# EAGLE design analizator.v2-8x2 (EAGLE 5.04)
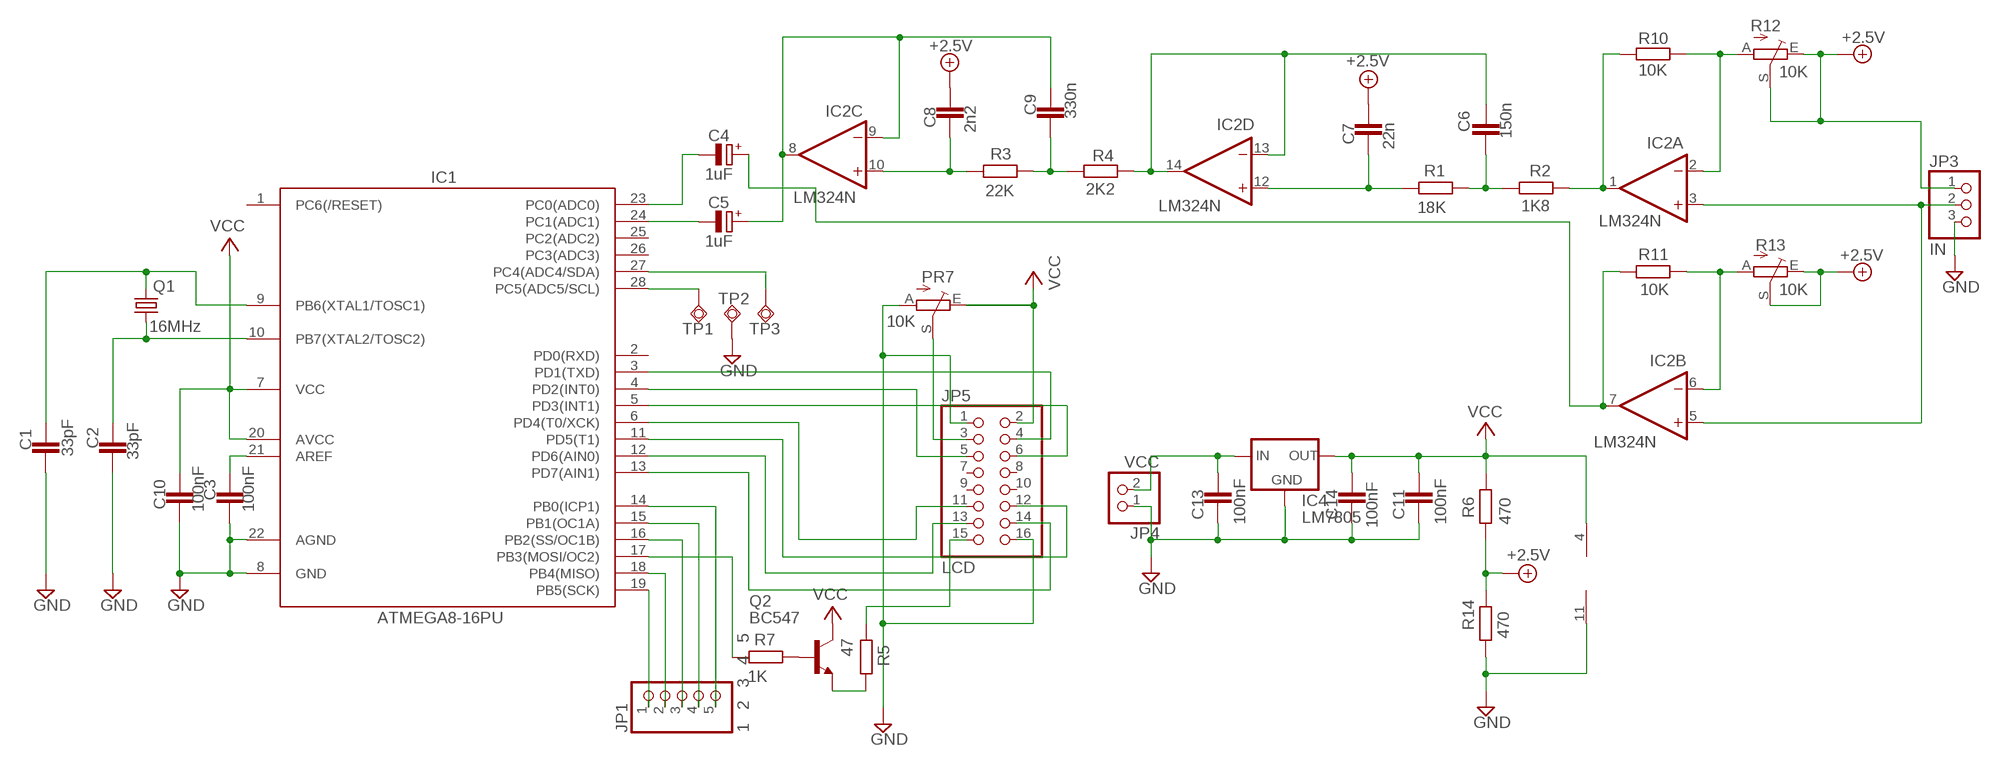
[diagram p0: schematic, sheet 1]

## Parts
C1  33pF  C-EU025-024X044  [C025-024X044]
C2  33pF  C-EU025-024X044  [C025-024X044]
C3  100nF  C-EU050-025X075  [C050-025X075]
C4  1uF  CPOL-EUE5-4  [E5-4]
C5  1uF  CPOL-EUE5-4  [E5-4]
C6  150n  C-EU050-025X075  [C050-025X075]
C7  22n  C-EU050-025X075  [C050-025X075]
C8  2n2  C-EU050-025X075  [C050-025X075]
C9  330n  C-EU050-025X075  [C050-025X075]
C10  100nF  C-EU050-025X075  [C050-025X075]
C11  100nF  C-EU050-025X075  [C050-025X075]
C13  100nF  C-EU050-025X075  [C050-025X075]
C14  100nF  C-EU050-025X075  [C050-025X075]
IC1  ATMEGA8-16PU  ATMEGA8-PU  [DIL28-3]
IC2  LM324N  [DIL14]
IC4  LM7805  78XXL  [78XXL]
JP1  1 2 3 4 5  PINHD-1X5  [1X05]
JP3  IN  PINHD-1X3  [1X03]
JP4  VCC  PINHD-1X2  [1X02]
JP5  LCD  PINHD-2X8  [2X08]
PR7  10K  TRIM_EU-CA6V  [CA6V]
Q1  16MHz  CRYTALHC49S  [HC49/S]
Q2  BC547  [TO92]
R1  18K  R-EU_0204/7  [0204/7]
R2  1K8  R-EU_0204/7  [0204/7]
R3  22K  R-EU_0204/7  [0204/7]
R4  2K2  R-EU_0204/7  [0204/7]
R5  47  R-EU_0204/7  [0204/7]
R6  470  R-EU_0204/7  [0204/7]
R7  1K  R-EU_0204/7  [0204/7]
R10  10K  R-EU_0204/7  [0204/7]
R11  10K  R-EU_0204/7  [0204/7]
R12  10K  TRIM_EU-CA6V  [CA6V]
R13  10K  TRIM_EU-CA6V  [CA6V]
R14  470  R-EU_0204/7  [0204/7]
TP1  TPSQTP11SQ  [TP11SQ]
TP2  TPSQTP11SQ  [TP11SQ]
TP3  TPSQTP11SQ  [TP11SQ]

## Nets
+5V: C7.1 C8.1 JP3.1 R6.1 R12.E R12.S R13.E R13.S R14.2 ; supply symbol labelled +2.5V
GND: C1.1 C2.1 C3.1 C10.1 C11.2 C13.2 C14.2 IC1.8(GND) IC1.22(AGND) IC2.11(P:V-) IC4.GND JP3.3 JP4.1 JP5.1 JP5.16 PR7.A R14.1 TP2.TP
N$1: C1.2 IC1.9(PB6(XTAL1/TOSC1)) Q1.2
N$2: C2.2 IC1.10(PB7(XTAL2/TOSC2)) Q1.1
N$3: C4.- IC1.23(PC0(ADC0))
N$4: C3.2 IC1.21(AREF)
N$5: C5.- IC1.24(PC1(ADC1))
N$6: C6.2 IC2.13(D:-IN) IC2.14(D:OUT) R4.2
N$7: C5.+ C9.2 IC2.8(C:OUT) IC2.9(C:-IN)
N$8: JP5.3 PR7.S
N$9: C7.2 IC2.12(D:+IN) R1.1
N$10: C6.1 R1.2 R2.1
N$11: IC1.3(PD1(TXD)) JP5.4
N$12: C8.2 IC2.10(C:+IN) R3.1
N$13: C9.1 R3.2 R4.1
N$14: IC1.4(PD2(INT0)) JP5.5
N$15: IC2.2(A:-IN) R10.2 R12.A
N$16: IC2.6(B:-IN) R11.2 R13.A
N$17: IC1.5(PD3(INT1)) JP5.6
N$18: IC1.6(PD4(T0/XCK)) JP5.11
N$19: IC1.11(PD5(T1)) JP5.12
N$20: IC1.12(PD6(AIN0)) JP5.13
N$21: IC1.13(PD7(AIN1)) JP5.14
N$22: IC1.17(PB3(MOSI/OC2)) R7.1
N$23: Q2.1(E) R5.2
N$24: IC2.3(A:+IN) IC2.5(B:+IN) JP3.2
N$25: Q2.2(B) R7.2
N$26: IC2.1(A:OUT) R2.2 R10.1
N$27: C4.+ IC2.7(B:OUT) R11.1
N$28: IC1.19(PB5(SCK)) JP1.1
N$29: JP5.15 R5.1
N$30: IC1.18(PB4(MISO)) JP1.2
N$31: IC1.16(PB2(SS/OC1B)) JP1.3
N$32: IC1.15(PB1(OC1A)) JP1.4
N$33: IC1.28(PC5(ADC5/SCL)) TP1.TP
N$38: IC1.14(PB0(ICP1)) JP1.5
N$39: IC1.27(PC4(ADC4/SDA)) TP3.TP
NS$28: C13.1 IC4.IN JP4.2
VCC: C10.2 C11.1 C14.1 IC1.7(VCC) IC1.20(AVCC) IC2.4(P:V+) IC4.OUT JP5.2 PR7.E Q2.3(C) R6.2
Unconnected: IC1.1(PC6(/RESET)) IC1.2(PD0(RXD)) IC1.25(PC2(ADC2)) IC1.26(PC3(ADC3)) JP5.7 JP5.8 JP5.9 JP5.10

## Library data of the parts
C1-C3 C6-C11 C13 C14 = rcl:C-EU: CAPACITOR, European symbol
C4 C5 = rcl:CPOL-EU: POLARIZED CAPACITOR, European symbol
IC1 = atmega8:ATMEGA8-PU
IC2 = linear:LM324: OP AMP
IC4 = v-reg:78XXL: VOLTAGE REGULATOR
JP1 = pinhead:PINHD-1X5: PIN HEADER
JP3 = pinhead:PINHD-1X3: PIN HEADER
JP4 = pinhead:PINHD-1X2: PIN HEADER
JP5 = pinhead:PINHD-2X8: PIN HEADER
PR7 R12 R13 = pot:TRIM_EU-: POTENTIOMETER
Q1 = crystal:CRYTAL: CRYSTAL
Q2 = transistor-npn:BC547*: NPN Transistor
R1-R7 R10 R11 R14 = rcl:R-EU_: RESISTOR, European symbol
TP1-TP3 = testpad:TPSQ

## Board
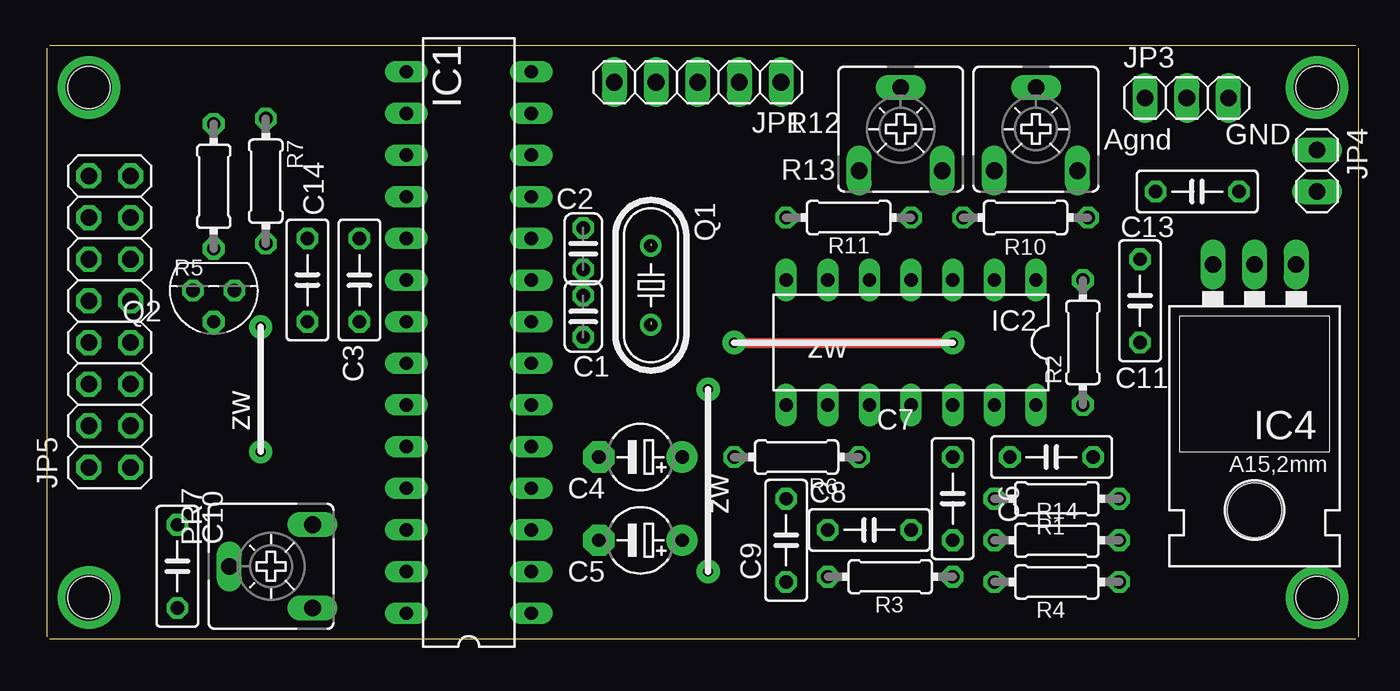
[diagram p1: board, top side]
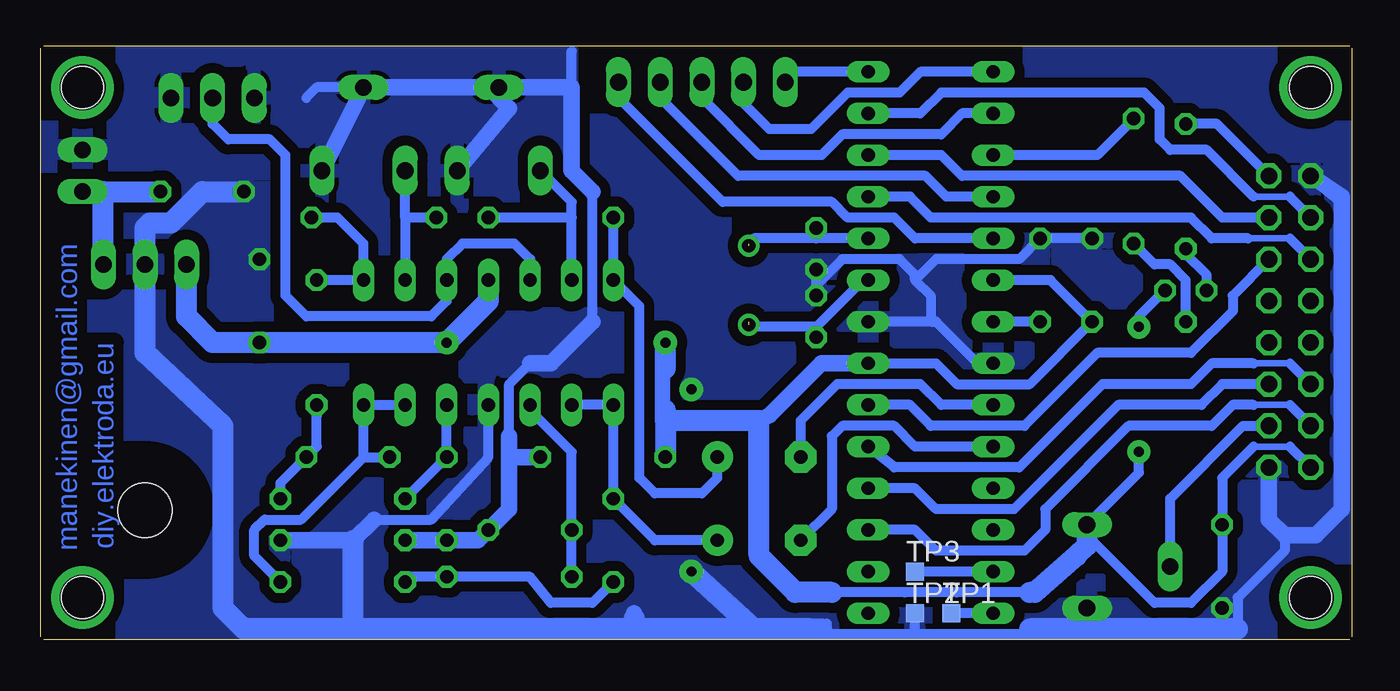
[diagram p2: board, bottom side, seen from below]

Size 80.01 x 36.2 mm. Coordinates in mm from the lower left corner, seen from the top.
Outline: 0,0.17 0,36.04
Outline: 79.85,36.2 0.17,36.2
Outline: 79.85,0 0.17,0
Outline: 80.01,0.17 80.01,36.04
Copper layers (1*16): Top 0.035mm / dielectric 1.5mm / Bottom 0.035mm
Design rules "default *": minimum track width 10mil, minimum drill 24mil, track to track 24mil, track to pad 24mil, pad to pad 24mil, via to via 24mil, smd to smd 24mil, copper to edge 1mil, drill to drill 8mil, minimum pad ring 10mil, minimum via ring 8mil, stop-mask expansion 4mil, vias tented up to drill 0mil, thermal gap 10mil
Holes 2.54 mm at 2.54,33.66 2.54,2.55 77.47,2.55 77.47,33.66

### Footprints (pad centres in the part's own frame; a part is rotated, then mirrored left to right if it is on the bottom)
C025-024X044 = drill 0.813 octagon: 1 -1.27,0; 2 1.27,0
C050-025X075 = drill 0.813 octagon: 1 -2.54,0; 2 2.54,0
E5-4 = drill 0.813 pad 1.905 round: + -2.54,0 | drill 0.813 pad 1.905 octagon: - 2.54,0
DIL28-3 = drill 0.813 long: 1 -16.51,-3.81; 2 -13.97,-3.81; 3 -11.43,-3.81; 4 -8.89,-3.81; 5 -6.35,-3.81; 6 -3.81,-3.81; 7 -1.27,-3.81; 8 1.27,-3.81; 9 3.81,-3.81; 10 6.35,-3.81; 11 8.89,-3.81; 12 11.43,-3.81; 13 13.97,-3.81; 14 16.51,-3.81; 15 16.51,3.81; 16 13.97,3.81; 17 11.43,3.81; 18 8.89,3.81; 19 6.35,3.81; 20 3.81,3.81; 21 1.27,3.81; 22 -1.27,3.81; 23 -3.81,3.81; 24 -6.35,3.81; 25 -8.89,3.81; 26 -11.43,3.81; 27 -13.97,3.81; 28 -16.51,3.81
DIL14 = drill 0.813 long: 1 -7.62,-3.81; 2 -5.08,-3.81; 3 -2.54,-3.81; 4 0,-3.81; 5 2.54,-3.81; 6 5.08,-3.81; 7 7.62,-3.81; 8 7.62,3.81; 9 5.08,3.81; 10 2.54,3.81; 11 0,3.81; 12 -2.54,3.81; 13 -5.08,3.81; 14 -7.62,3.81
78XXL = drill 1.016 long: GND 0,-3.81; IN -2.54,-3.81; OUT 2.54,-3.81 | hole 3.302: 0,11.176
1X05 = drill 1.016 long: 1 -5.08,0; 2 -2.54,0; 3 0,0; 4 2.54,0; 5 5.08,0
1X03 = drill 1.016 long: 1 -2.54,0; 2 0,0; 3 2.54,0
1X02 = drill 1.016 long: 1 -1.27,0; 2 1.27,0
2X08 = drill 1.016 octagon: 1 -8.89,-1.27; 2 -8.89,1.27; 3 -6.35,-1.27; 4 -6.35,1.27; 5 -3.81,-1.27; 6 -3.81,1.27; 7 -1.27,-1.27; 8 -1.27,1.27; 9 1.27,-1.27; 10 1.27,1.27; 11 3.81,-1.27; 12 3.81,1.27; 13 6.35,-1.27; 14 6.35,1.27; 15 8.89,-1.27; 16 8.89,1.27
CA6V = drill 1.016 long: A -2.54,-2.54; E 2.54,-2.54; S 0,2.54
HC49/S = drill 0.813 round: 1 -2.413,0; 2 2.413,0
TO92 = drill 0.813 octagon: 1 1.27,0; 2 0,1.905; 3 -1.27,0
0204/7 = drill 0.813 octagon: 1 -3.81,0; 2 3.81,0
TP11SQ = smd 1.1 x 1.1: TP 0,0

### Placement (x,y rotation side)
C1  32.71,19.69 270 top
C2  32.71,23.82 90 top
C3  19.05,21.91 270 top
C4  36.2,11.12 180 top
C5  36.2,6.04 180 top
C6  61.28,11.12 180 top
C7  55.25,8.58 90 top
C8  50.17,6.67 180 top
C9  45.09,6.04 90 top
C10  7.94,4.45 90 top
C11  66.68,20.64 90 top
C13  70.17,27.31 180 top
C14  15.88,21.91 90 top
IC1  25.72,18.1 90 top
IC2  52.71,18.1 180 top
IC4  73.67,19.05 180 top
JP1  39.69,33.98 180 top
JP3  69.54,33.02 0 top
JP4  77.47,28.58 270 top
JP5  3.82,19.37 90 top
PR7  13.66,4.45 90 top
Q1  36.84,21.6 270 top
Q2  10.16,21.28 180 top
R1  61.6,8.58 0 top
R2  63.19,18.1 90 top
R3  51.44,3.81 0 top
R4  61.6,3.5 0 top
R5  10.16,27.63 270 top
R6  45.73,11.12 180 top
R7  13.34,27.95 270 top
R10  59.7,25.72 180 top
R11  48.9,25.72 0 top
R12  60.33,31.12 0 top
R13  52.08,31.12 0 top
R14  61.6,6.04 180 top
TP1  24.45,1.59 0 bottom
TP2  26.68,1.59 0 bottom
TP3  26.68,4.13 0 bottom

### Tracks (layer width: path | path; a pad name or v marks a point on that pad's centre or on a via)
+5V
  Bottom 0.61: 46.36,19.37 46.36,27.31 | 50.17,16.83 51.44,15.56 51.44,12.39 | R12.S 63.19,33.66 63.82,33.02 | 47.63,33.66 47.63,35.88
  Bottom 1.016: 52.71,33.66 R13.S 47.63,33.66 47.63,28.58 46.36,27.31 | 52.71,33.66 R12.S R12.E | R13.E 51.44,32.39 52.71,33.66 | 46.36,19.37 48.9,16.83 50.17,16.83 | 51.44,11.12 51.44,7.94 C8.1 53.34,6.04 C7.1 R14.2 | 51.44,11.12 51.44,12.39 | 51.44,11.12 R6.1
  pour Bottom: 44.45,20.64 53.98,20.64 53.98,15.56 44.45,15.56
  pour Bottom: 67.31,36.2 64.78,20.64 47.63,20.64 47.63,35.88
GND  (via drill 0.6 pad 1.42)
  Top 0.406: v40.33,4.13 v40.33,15.24
  Bottom 0.61: IC1.22 22.86,16.83 25.41,19.37 25.72,19.37 | 25.72,19.37 IC1.8 | IC2.11 52.71,11.12 56.2,7.31 59.7,7.31 | 26.68,21.91 25.41,23.18 20.32,23.18 C3.1 C14.2 | 32.71,21.6 31.12,23.18 27.63,23.18 26.68,22.23 26.68,21.91 | 32.71,21.6 C2.1 | 32.71,21.6 C1.1 | 32.07,0.96 33.02,0.64 32.07,0.32 26.68,0.32 | 26.68,0.32 20.01,0.32 19.69,0.64 6.99,0.64 6.99,1.91 | 26.68,21.91 25.72,20.96 25.72,19.37 | 6.99,1.91 C10.1 | 6.99,1.91 6.99,2.55 4.13,5.4 4.13,6.36 | 16.2,0.64 PR7.A | 26.68,0.32 TP2.TP
  Bottom 0.813: JP5.16 0.96,26.99
  Bottom 1.016: 59.7,7.31 60.96,6.04 R14.1 | 43.82,1.27 43.82,1.59 | JP5.16 0.64,26.99 0.64,7.94 2.23,6.36 4.13,6.36 5.08,7.31 JP5.1
  Bottom 1.27: 32.39,0.64 33.02,0.64 36.52,0.64 | 36.52,0.64 43.82,0.64 | 43.82,0.64 43.82,1.27 | 43.82,0.64 60.96,0.64 | 60.96,0.64 67.63,0.64 68.9,1.91 68.9,13.02 73.67,17.47 73.67,25.09 73.35,25.41 72.08,25.41 70.17,27.31 C13.2 | 60.96,0.64 60.96,6.04 | 6.99,0.64 16.2,0.64 19.69,0.64 | 36.52,0.64 v40.33,4.13
  pour Bottom: -0.63,35.88 -0.63,0.32 80.02,0.32 80.02,35.88
N$1  (1 unrouted)
  Bottom 0.61: IC1.9 29.85,21.91 32.71,19.05 | C1.2 32.71,19.05 | 32.71,19.05 36.52,19.05 36.84,19.37
N$2  (1 unrouted)
  Bottom 0.61: IC1.10 32.71,24.45 | 32.71,24.45 C2.2 | 32.71,24.45 36.52,24.45 36.84,24.14
N$3
  Bottom 0.61: IC1.23 25.09,14.29 26.36,15.56 31.44,15.56 33.66,13.34 C4.-
N$4
  Bottom 0.61: C3.2 IC1.21
N$5
  Bottom 0.61: IC1.24 26.68,11.75 27.95,13.02 31.12,13.02 31.76,12.39 31.76,7.94 C5.-
N$6
  Bottom 0.61: R4.2 67,5.09 67,6.67 66.36,7.31 64.14,7.31 60.33,11.12 | IC2.13 IC2.14 60.33,11.12 | 60.33,11.12 C6.2
N$7
  Bottom 0.61: C5.+ 42.55,6.04 C9.2 IC2.8 IC2.9
N$8
  Bottom 0.61: PR7.S 11.12,8.58 6.67,13.02 JP5.3
N$9
  Bottom 0.61: IC2.12 C7.2 R1.1
N$10
  Bottom 0.61: 63.19,13.66 R2.1 63.19,11.75 C6.1 65.41,9.53 R1.2
N$11
  Bottom 0.406: 3.82,14.29 6.04,14.29
  Bottom 0.61: IC1.3 26.68,6.67 25.41,5.4 20.01,5.4 18.74,6.67 18.74,7.94 13.66,13.02 8.58,13.02 7.31,14.29 6.04,14.29 | JP5.4 3.82,14.29
N$12
  Bottom 0.61: IC2.10 50.17,13.97 47.63,11.44 C8.2 R3.1
N$13
  Bottom 0.61: C9.1 46.36,2.23 48.9,2.23 50.17,3.81 R3.2 57.16,3.81 57.47,3.81 R4.1
N$14
  Bottom 0.61: IC1.4 26.68,9.21 25.41,7.94 20.64,7.94 14.29,14.29 9.21,14.29 7.94,15.56 JP5.5
N$15
  Bottom 0.61: 57.79,25.72 IC2.2 | 57.79,25.72 R12.A | R10.2 57.79,25.72
N$16
  Bottom 0.61: IC2.6 47.63,25.72 | 47.63,25.72 47.63,26.68 R13.A | 47.63,25.72 R11.2
N$17
  Bottom 0.406: 3.82,16.83 6.04,16.83
  Bottom 0.61: IC1.5 27.95,10.48 20.32,10.48 15.25,15.56 9.85,15.56 8.58,16.83 6.04,16.83 | JP5.6 3.82,16.83
N$18
  Bottom 0.61: IC1.6 26.99,14.29 25.72,13.02 20.01,13.02 15.56,17.47 9.85,17.47 7.31,20.01 7.31,20.96 JP5.11
N$19
  Bottom 0.406: 3.82,24.45 6.36,24.45
  Bottom 0.61: IC1.11 26.99,26.99 25.72,25.72 9.85,25.72 8.58,24.45 6.36,24.45 | JP5.12 3.82,24.45
N$20
  Bottom 0.61: IC1.12 25.09,29.53 23.82,28.26 10.48,28.26 7.94,25.72 JP5.13
N$21
  Bottom 0.406: 3.82,26.99 6.04,26.99
  Bottom 0.61: IC1.13 26.36,32.07 25.09,33.34 12.71,33.34 11.75,32.39 11.75,30.48 11.12,29.85 8.89,29.85 6.04,26.99 | JP5.14 3.82,26.99
N$22
  Bottom 0.61: R7.1 15.56,29.53 IC1.17
N$23
  Bottom 0.61: Q2.1 8.89,22.23 10.16,23.5 R5.2
N$24
  Bottom 0.61: IC2.5 50.17,23.18 51.12,24.14 54.3,24.14 55.25,23.18 IC2.3 55.25,20.64 56.2,19.69 63.82,19.69 65.09,20.96 65.09,29.53 66.05,30.48 68.58,30.48 69.54,31.44 JP3.2
N$25
  Bottom 0.61: R7.2 12.71,23.5 12.07,22.87 11.12,22.87 10.16,21.91 Q2.2
N$26
  Bottom 0.61: R2.2 IC2.1 60.33,24.14 61.92,25.72 R10.1
N$27
  Bottom 0.61: C4.+ 38.74,9.85 39.69,8.89 42.55,8.89 43.5,9.85 43.5,20.33 IC2.7 R11.1
N$28
  Bottom 0.61: IC1.19 26.68,24.45 27.95,25.72 30.8,25.72 31.76,26.68 38.42,26.68 44.77,33.02 JP1.1
N$29
  Bottom 0.61: JP5.15 8.26,31.44 R5.1
N$30
  Bottom 0.61: IC1.18 24.77,26.99 26.04,28.26 37.47,28.26 42.23,33.02 JP1.2
N$31
  Bottom 0.61: IC1.16 23.82,32.07 25.09,30.8 31.12,30.8 32.39,29.53 36.2,29.53 39.69,33.02 JP1.3
N$32
  Bottom 0.61: IC1.15 26.36,34.61 27.63,33.34 30.8,33.34 33.02,31.12 35.56,31.12 37.15,32.71 JP1.4
N$33
  Bottom 0.61: IC1.28 TP1.TP
N$34  (via drill 2.8 pad 2.54)
  other vias: 2.54,33.66
N$35  (via drill 2.8 pad 2.54)
  other vias: 77.47,33.66
N$36  (via drill 2.8 pad 2.54)
  other vias: 2.54,2.55
N$37  (via drill 2.8 pad 2.54)
  other vias: 77.47,2.55
N$38
  Bottom 0.61: IC1.14 33.98,34.61 JP1.5
N$39
  Bottom 0.61: IC1.27 TP3.TP
NS$28
  Bottom 1.27: 76.2,27.31 C13.1 | 76.2,27.31 JP4.2 | IC4.IN 76.2,27.31
VCC  (via drill 0.6 pad 1.42, 0.61 pad 1.42)
  Top 0.406: v13.02,11.44 v13.02,19.05
  Top 0.61: v41.91,18.1 v55.25,18.1
  Bottom 0.406: 3.82,11.75 6.04,11.75
  Bottom 0.61: 19.69,2.86 24.13,2.86 27.31,2.86 31.76,2.86 | IC1.20 18.42,21.91 C14.1 19.69,15.56 24.13,15.56 25.41,16.83 IC1.7 | 41.91,13.97 41.91,16.52 | JP5.2 3.82,11.75 | 6.04,11.75 7.94,9.85 C10.2 7.94,4.13 9.85,2.23 12.07,2.23 16.2,6.36 PR7.E 13.02,10.16 v13.02,11.44 | 41.91,13.34 42.23,13.66 42.23,17.79 v41.91,18.1 | Q2.3 13.02,19.69 v13.02,19.05
  Bottom 1.016: 36.2,13.34 35.56,13.66 32.39,16.83 IC1.7
  Bottom 1.27: PR7.E 16.2,5.72 16.83,5.09 19.37,2.86 19.69,2.86 | 31.76,2.86 33.98,2.86 36.2,5.09 36.2,13.34 41.91,13.34 | IC2.4 52.71,20.64 v55.25,18.1 C11.1 69.54,18.1 71.12,19.69 IC4.OUT | 41.91,13.34 R6.2 | 41.91,16.52 v41.91,18.1 | 41.91,13.34 41.91,13.97

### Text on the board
Bottom: manekinen@gmail.com | diy.elektroda.eu
tPlace: GND | Agnd | zw | zw | zw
